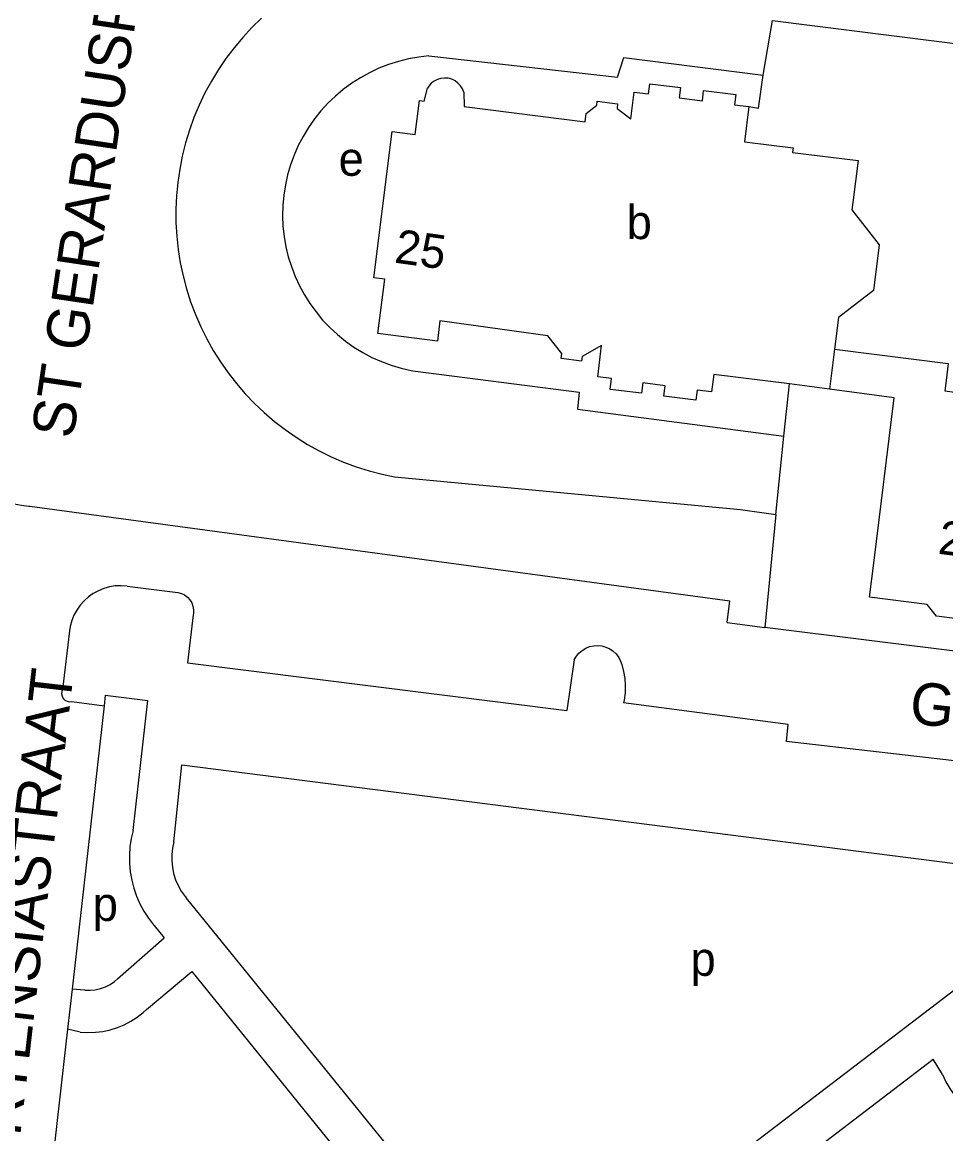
# Model space of a CAD drawing. Extents: x 161258 to 163262, y 380749 to 382054.
# Drawn here: x 162036.2 to 162145.4, y 381182.5 to 381313.9 of the extents above; entities that cross this region are included whole.
import ezdxf

# ---------------------------------------------------------------- set-up
doc = ezdxf.new("R2010")
doc.units = 0
for name, color, linetype in [('BLT_Basislijn', 7, 'Continuous'), ('BLT_Bebouwing', 7, 'Continuous'), ('BLT_Centroide', 7, 'Continuous'), ('BLT_Huisnummer', 7, 'Continuous'), ('BLT_Huisnummer_reeks', 7, 'Continuous'), ('BLT_Onderverdeling_panden', 7, 'Continuous'), ('BLT_Straatnaam', 7, 'Continuous')]:
    doc.layers.add(name, color=color, linetype=linetype)

msp = doc.modelspace()

# ---------------------------------------------------------------- linework, layer by layer
at = {"layer": 'BLT_Basislijn'}
for p, q in [((162123.8, 381307.68), (162124.92, 381314.14)), ((162124.92, 381314.14), (162169.61, 381308.51)), ((162126.27, 381265), (162126.93, 381271.2)), ((162125.3, 381255.76), (162126.27, 381265)), ((162080.23, 381260.2), (162121.13, 381256.34)), ((162037.13, 381256.74), (162119.86, 381245.53)), ((162121.13, 381256.34), (162125.3, 381255.76)), ((162125.3, 381255.76), (162124.02, 381242.41)), ((162048.62, 381247.27), (162054.63, 381246.54)), ((162119.56, 381242.99), (162119.86, 381245.53)), ((162056.45, 381243.9), (162055.78, 381238.21)), ((162041.8, 381241.99), (162040.98, 381235.08)), ((162119.56, 381242.99), (162124.02, 381242.41)), ((162188.57, 381234.31), (162124.02, 381242.41)), ((162055.78, 381238.21), (162100.6, 381232.57)), ((162101.47, 381238.58), (162100.6, 381232.57)), ((162046.04, 381234.4), (162045.9, 381233.12)), ((162046.04, 381234.4), (162051.06, 381233.76)), ((162042.07, 381233.63), (162045.9, 381233.12)), ((162045.9, 381233.12), (162042.11, 381199.62)), ((162049.34, 381218.39), (162051.06, 381233.76)), ((162054.16, 381217.05), (162055.11, 381226.14)), ((162055.11, 381226.14), (162149.92, 381214.06)), ((162081.47, 381178.6), (162055.63, 381210.41)), ((162051.84, 381207.15), (162053, 381205.72)), ((162047.49, 381200.85), (162053, 381205.72)), ((162050.93, 381197.22), (162056.26, 381201.71)), ((162056.26, 381201.71), (162079.29, 381173.36)), ((162042.11, 381199.62), (162041.57, 381194.89)), ((162043.61, 381199.53), (162042.11, 381199.62)), ((162146.49, 381199.55), (162112.51, 381173.67)), ((162041.57, 381194.89), (162038.71, 381169.6)), ((162043.09, 381194.56), (162041.57, 381194.89)), ((162120.26, 381173.31), (162143.9, 381191.37)), ((162145.02, 381189.53), (162143.9, 381191.37))]:
    msp.add_line(p, q, dxfattribs=at)
for points in [[(162064.51, 381314.42), (162063.37, 381313.31), (162062.29, 381312.15), (162061.27, 381310.93), (162060.31, 381309.66), (162059.41, 381308.35), (162058.59, 381306.99), (162057.83, 381305.59), (162057.14, 381304.16), (162056.53, 381302.69), (162055.99, 381301.2), (162055.53, 381299.67), (162055.15, 381298.13), (162054.84, 381296.57), (162054.61, 381295), (162054.46, 381293.42), (162054.39, 381291.83), (162054.4, 381290.24), (162054.49, 381288.65), (162054.66, 381287.07), (162054.91, 381285.5), (162055.24, 381283.95), (162055.65, 381282.41), (162056.13, 381280.9), (162056.69, 381279.41), (162057.32, 381277.95), (162058.03, 381276.53), (162058.81, 381275.14), (162059.65, 381273.79), (162060.56, 381272.49), (162061.54, 381271.24), (162062.58, 381270.03), (162063.67, 381268.88), (162064.83, 381267.79), (162066.03, 381266.76), (162067.29, 381265.78), (162068.6, 381264.88), (162069.94, 381264.04), (162071.33, 381263.26), (162072.76, 381262.56), (162074.22, 381261.93), (162075.71, 381261.38), (162077.23, 381260.9), (162078.76, 381260.5), (162080.23, 381260.2)], [(162084.31, 381309.96), (162083.1, 381309.82), (162081.89, 381309.61), (162080.7, 381309.32), (162079.53, 381308.94), (162078.39, 381308.5), (162077.28, 381307.98), (162076.2, 381307.39), (162075.17, 381306.73), (162074.18, 381306), (162073.24, 381305.21), (162072.36, 381304.37), (162071.53, 381303.46), (162070.76, 381302.51), (162070.06, 381301.5), (162069.42, 381300.45), (162068.86, 381299.37), (162068.36, 381298.24), (162067.94, 381297.09), (162067.6, 381295.92), (162067.33, 381294.72), (162067.14, 381293.51), (162067.03, 381292.29), (162067, 381291.06), (162067.05, 381289.84), (162067.18, 381288.62), (162067.39, 381287.41), (162067.68, 381286.22), (162068.05, 381285.05), (162068.49, 381283.9), (162069, 381282.79), (162069.59, 381281.71), (162070.24, 381280.68), (162070.96, 381279.69), (162071.74, 381278.74), (162072.59, 381277.85), (162073.49, 381277.02), (162074.44, 381276.25), (162075.44, 381275.54), (162076.49, 381274.9), (162077.57, 381274.33), (162078.69, 381273.83), (162079.84, 381273.4), (162081.01, 381273.05), (162082.21, 381272.78), (162082.41, 381272.74)], [(162084.31, 381309.96), (162106.59, 381307.47), (162107.34, 381309.76), (162123.8, 381307.68)], [(162122.14, 381303.97), (162123.25, 381303.79), (162123.8, 381307.68)], [(162082.41, 381272.74), (162102.05, 381270.2), (162101.86, 381268.2), (162126.27, 381265)], [(162027.77, 381267.68), (162027.71, 381266.79), (162027.74, 381265.9), (162027.84, 381265.02), (162028.02, 381264.15), (162028.29, 381263.3), (162028.62, 381262.48), (162029.03, 381261.68), (162029.51, 381260.93), (162030.05, 381260.23), (162030.65, 381259.58), (162031.32, 381258.98), (162032.03, 381258.45), (162032.78, 381257.98), (162033.58, 381257.59), (162034.4, 381257.26), (162035.26, 381257.01), (162036.13, 381256.84), (162037.01, 381256.75), (162037.13, 381256.74)], [(162048.62, 381247.27), (162047.93, 381247.32), (162047.23, 381247.3), (162046.54, 381247.19), (162045.87, 381247), (162045.23, 381246.74), (162044.62, 381246.41), (162044.05, 381246.01), (162043.53, 381245.54), (162043.07, 381245.02), (162042.67, 381244.45), (162042.33, 381243.84), (162042.07, 381243.2), (162041.89, 381242.52), (162041.8, 381241.99)], [(162054.63, 381246.54), (162055.04, 381246.43), (162055.42, 381246.24), (162055.75, 381245.98), (162056.04, 381245.66), (162056.26, 381245.3), (162056.4, 381244.9), (162056.48, 381244.48), (162056.47, 381244.05), (162056.45, 381243.9)], [(162101.47, 381238.58), (162101.73, 381239), (162102.04, 381239.37), (162102.42, 381239.69), (162102.84, 381239.95), (162103.3, 381240.13), (162103.78, 381240.23), (162104.27, 381240.26), (162104.76, 381240.21), (162105.23, 381240.08), (162105.68, 381239.87), (162106.09, 381239.59), (162106.44, 381239.26), (162106.74, 381238.86), (162106.97, 381238.43), (162107.11, 381238.03)], [(162107.11, 381238.03), (162107.32, 381237.2), (162107.46, 381236.36), (162107.52, 381235.51), (162107.49, 381234.65), (162107.39, 381233.8), (162107.32, 381233.47)], [(162040.98, 381235.08), (162040.89, 381234.81), (162040.87, 381234.53), (162040.93, 381234.26), (162041.07, 381234.01), (162041.27, 381233.81), (162041.52, 381233.67), (162041.79, 381233.61), (162042.07, 381233.63)], [(162159.39, 381226.92), (162158.05, 381226.93), (162158.05, 381225.29), (162126.58, 381228.93), (162126.76, 381230.93), (162107.32, 381233.47)], [(162049.34, 381218.39), (162049.11, 381217.43), (162048.96, 381216.46), (162048.9, 381215.47), (162048.91, 381214.48), (162049, 381213.5), (162049.17, 381212.53), (162049.41, 381211.57), (162049.74, 381210.64), (162050.14, 381209.73), (162050.61, 381208.86), (162051.15, 381208.04), (162051.75, 381207.25), (162051.84, 381207.15)], [(162054.16, 381217.05), (162053.99, 381216.31), (162053.9, 381215.55), (162053.9, 381214.79), (162053.97, 381214.04), (162054.12, 381213.3), (162054.35, 381212.57), (162054.65, 381211.88), (162055.03, 381211.22), (162055.47, 381210.6), (162055.63, 381210.41)], [(162043.61, 381199.53), (162044.24, 381199.51), (162044.86, 381199.56), (162045.47, 381199.7), (162046.06, 381199.91), (162046.62, 381200.19), (162047.14, 381200.54), (162047.49, 381200.85)], [(162043.09, 381194.56), (162043.98, 381194.51), (162044.87, 381194.54), (162045.75, 381194.64), (162046.62, 381194.83), (162047.47, 381195.09), (162048.29, 381195.43), (162049.08, 381195.84), (162049.83, 381196.32), (162050.54, 381196.86), (162050.93, 381197.22)], [(162145.02, 381189.53), (162145.41, 381188.69), (162145.88, 381187.9), (162146.41, 381187.14), (162147.01, 381186.43), (162147.66, 381185.78), (162148.37, 381185.19), (162149.13, 381184.66), (162149.93, 381184.2), (162150.77, 381183.8), (162151.64, 381183.49), (162152.28, 381183.31)]]:
    msp.add_lwpolyline(points, dxfattribs=at)
at = {"layer": 'BLT_Bebouwing'}
for points in [[(162088.42, 381305.67), (162088.26, 381306.07), (162088.03, 381306.44), (162087.73, 381306.76), (162087.39, 381307.01), (162087, 381307.2), (162086.58, 381307.32), (162086.15, 381307.35), (162085.72, 381307.31), (162085.31, 381307.19), (162084.92, 381306.99), (162084.58, 381306.73), (162084.29, 381306.4), (162084.14, 381306.17)], [(162088.42, 381305.67), (162088.46, 381303.97), (162102.77, 381302.19), (162102.89, 381303.17), (162104.14, 381304.14), (162104.2, 381304.61), (162106.61, 381304.31), (162106.54, 381303.75), (162108.17, 381302.52), (162108.56, 381305.68), (162110.25, 381305.47), (162110.4, 381306.67), (162114.04, 381306.22), (162113.89, 381305), (162116.63, 381304.66), (162116.78, 381305.86), (162120.58, 381305.39), (162120.43, 381304.19), (162122.14, 381303.97)], [(162126.93, 381271.2), (162117.98, 381272.31), (162117.72, 381270.24), (162116.02, 381270.46), (162115.87, 381269.26), (162112.09, 381269.73), (162112.24, 381270.98), (162109.59, 381271.31), (162109.43, 381270.08), (162105.74, 381270.54), (162105.9, 381271.81), (162104.26, 381272.01), (162104.72, 381275.73), (162102.42, 381274.42), (162102.35, 381273.89), (162099.92, 381274.19), (162100, 381274.8), (162098.37, 381276.89), (162085.6, 381278.66), (162085.3, 381276.26), (162078.28, 381277.13), (162079.08, 381283.57), (162077.81, 381283.73), (162079.96, 381301.03), (162082.67, 381300.69), (162083.17, 381304.68), (162083.73, 381304.61), (162084.14, 381306.17)], [(162122.14, 381303.97), (162121.62, 381299.8), (162127.37, 381299.09), (162127.3, 381298.55), (162135.04, 381297.59), (162134.42, 381292.63), (162134.31, 381291.75), (162137.52, 381287.62), (162136.85, 381282.25), (162132.72, 381279.03), (162132.25, 381275.28)], [(162145.44, 381271.6), (162145.28, 381270.36), (162146.74, 381270.18), (162146.87, 381271.18), (162149.35, 381270.87), (162151.3, 381286.98)], [(162132.25, 381275.28), (162145.69, 381273.61), (162145.44, 381271.6)], [(162131.64, 381270.55), (162126.93, 381271.2)], [(162148.7, 381244.9), (162146.77, 381243.4), (162144.31, 381243.72), (162143.22, 381245.13), (162136.38, 381245.99), (162136.89, 381250), (162139.31, 381269.56), (162131.64, 381270.55)]]:
    msp.add_lwpolyline(points, dxfattribs=at)
at = {"layer": 'BLT_Onderverdeling_panden'}
msp.add_line((162132.25, 381275.28), (162131.64, 381270.55), dxfattribs=at)

# ---------------------------------------------------------------- texts
at = {"layer": 'BLT_Centroide'}
for s, p in [('e', (162073.63, 381295.79)), ('b', (162107.68, 381288.31)), ('p', (162044.56, 381207.7)), ('p', (162115.23, 381201.21))]:
    msp.add_text(s, height=4, dxfattribs=at).set_placement(p)
at = {"layer": 'BLT_Huisnummer'}
msp.add_text('25', height=4, rotation=352.132, dxfattribs=at).set_placement((162080.12, 381285.54))
at = {"layer": 'BLT_Huisnummer_reeks'}
msp.add_text('26-34', height=4, rotation=352.9096, dxfattribs=at).set_placement((162144.39, 381251.12))
at = {"layer": 'BLT_Straatnaam'}
for s, height, rotation, p in [('ST GERARDUSPLEIN', 4.9999, 81.4987, (162042.24, 381264.59)), ('HORTENSIASTRAAT', 5, 83.4116, (162034.83, 381172.23)), ('GLADIOLUSSTRAAT', 5, 353.6443, (162140.97, 381231.09))]:
    msp.add_text(s, height=height, rotation=rotation, dxfattribs=at).set_placement(p)

doc.saveas('drawing.dxf')
